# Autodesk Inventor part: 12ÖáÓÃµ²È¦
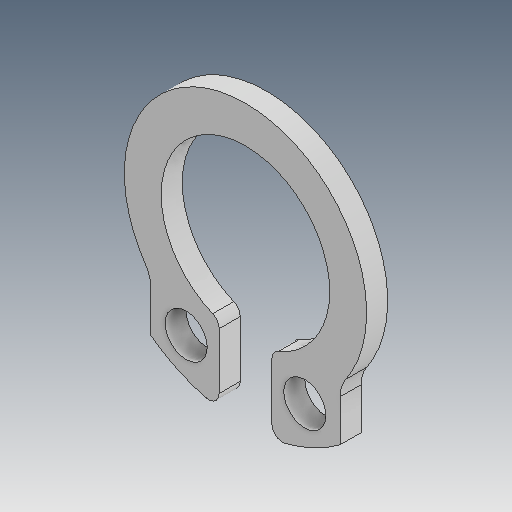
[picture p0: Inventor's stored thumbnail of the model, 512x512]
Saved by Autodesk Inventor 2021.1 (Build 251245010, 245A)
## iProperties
Created: 2019-04
Part Number: 12ÖáÓÃµ²È¦
Material: Ogólny
Document SubType Name: Modeling
Designer: user
Density: 1 g/cm^3
Appearance: Domyślna
Author: user
Revision Number: ÈÎºÎ
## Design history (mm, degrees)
feature "ÊäÈë1"
node "Bryła1"
